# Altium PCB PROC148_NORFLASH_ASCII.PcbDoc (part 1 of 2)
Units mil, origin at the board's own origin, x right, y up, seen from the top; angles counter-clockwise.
Board outline 790 x 790 mil, 6 copper layers (Top Layer, GND1, Signal Layer 1, Signal Layer 2, PWR/GND2, Bottom Layer), stack 65.134 mil thick; 36 components, 63 nets, 233 pads, 102 vias.
Unrouted connection lines stored in the file: 1.
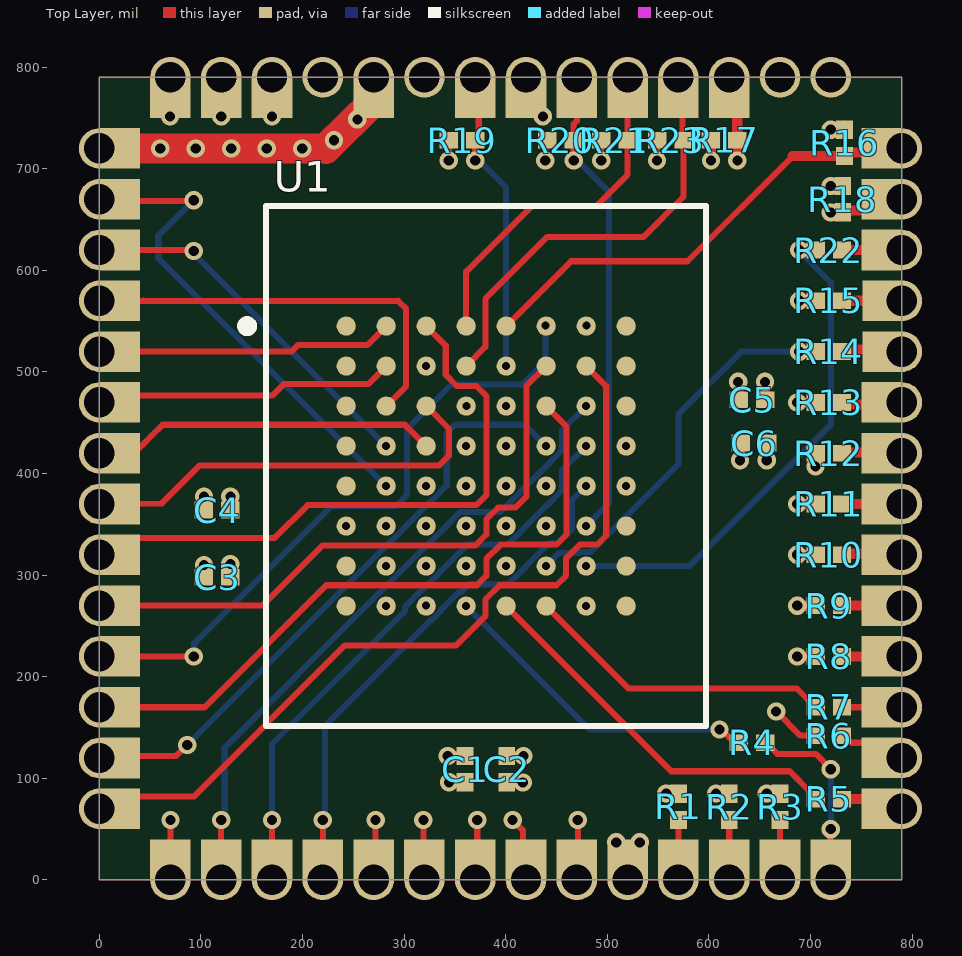
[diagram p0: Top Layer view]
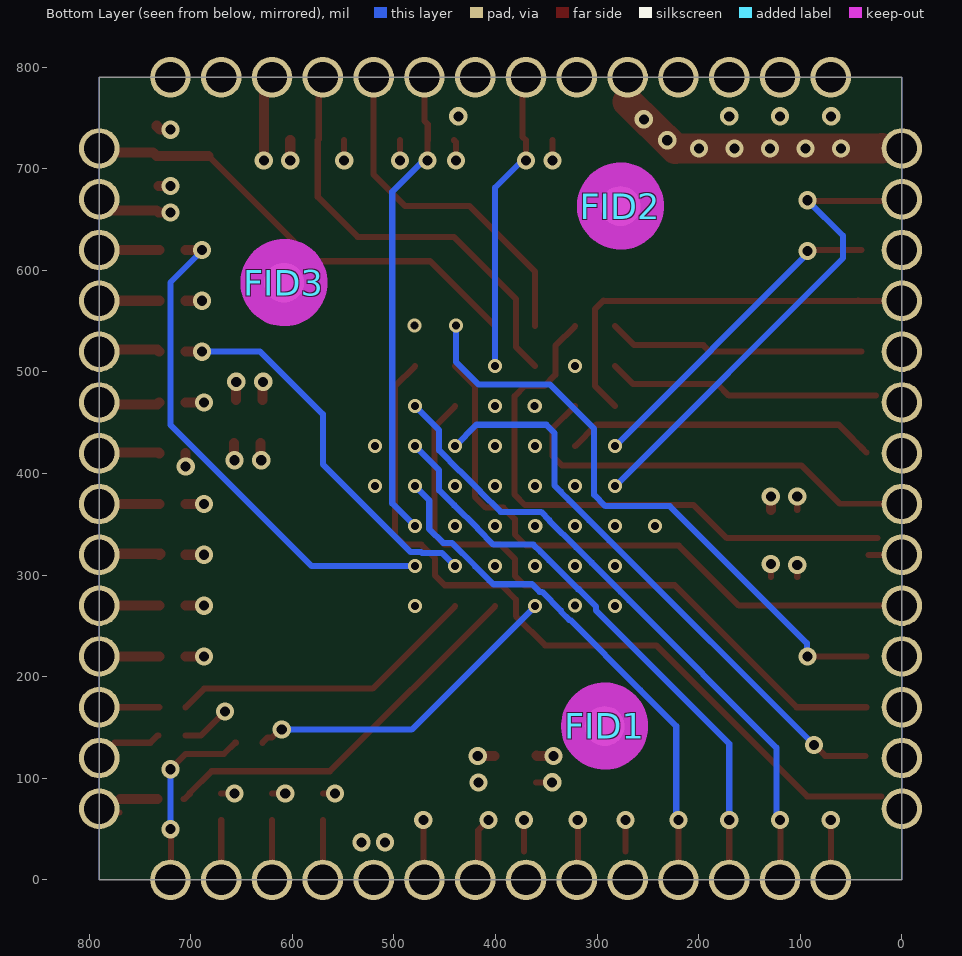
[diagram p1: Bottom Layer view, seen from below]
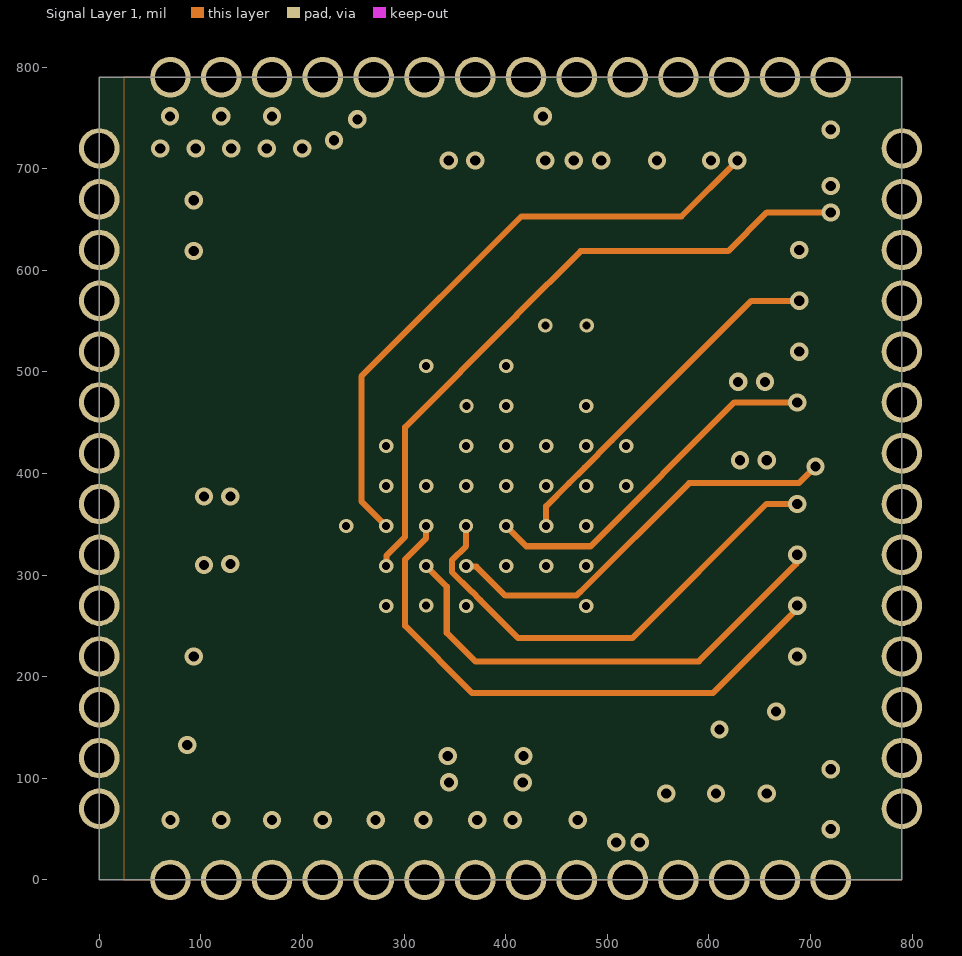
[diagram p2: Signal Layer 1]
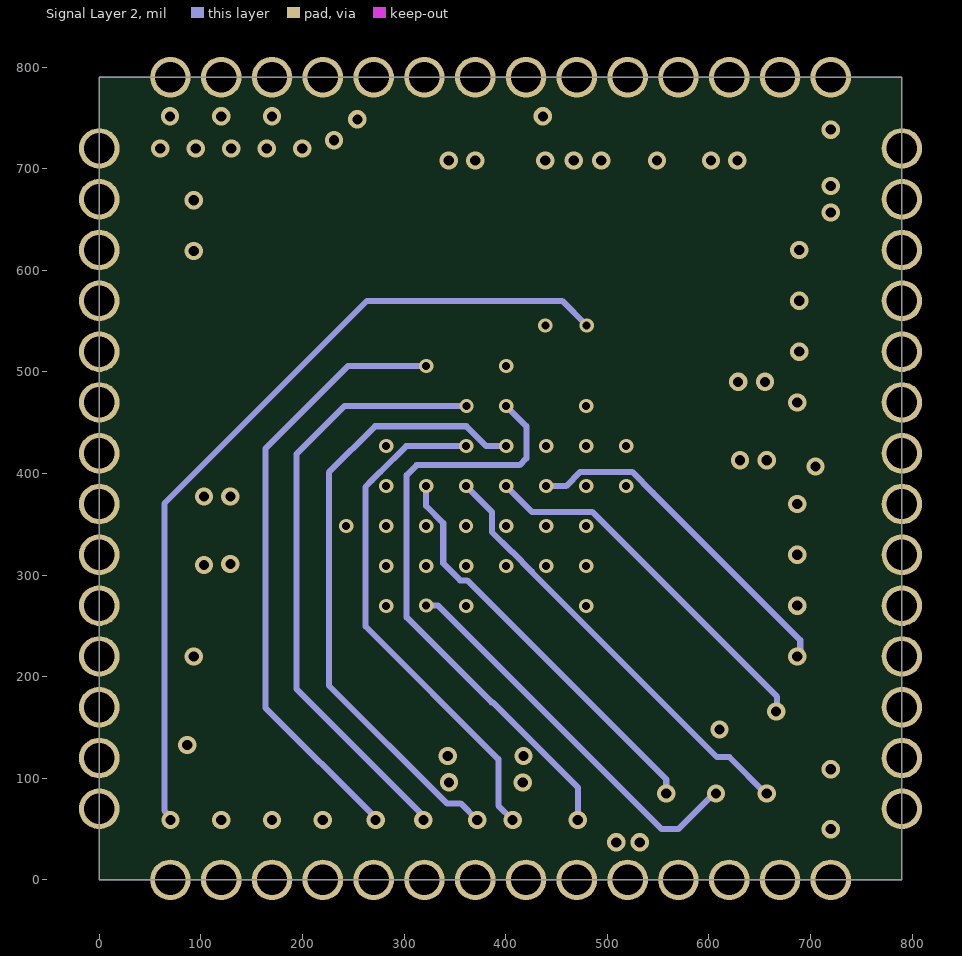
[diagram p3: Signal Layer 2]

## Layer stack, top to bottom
Top Solder: solder mask 0.4, Solder Resist, Dk 3.5
Top Layer: signal copper 0.689
Dielectric 1: prepreg 3.7, FR-4, Dk 4.1
GND1: signal copper 0.689
Dielectric 3: prepreg 2.8, PP-006, Dk 4.1
Signal Layer 1: signal copper 0.689
Dielectric1: core 48, FR-4, Dk 4.8
Signal Layer 2: signal copper 0.689
Dielectric 4: prepreg 2.8, PP-006, Dk 4.1
PWR/GND2: signal copper 0.689
Dielectric 2: prepreg 3.7, FR-4, Dk 4.1
Bottom Layer: signal copper 0.689
Bottom Solder: solder mask 0.4, Solder Resist, Dk 3.5

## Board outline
0,0 790,0 790,790 0,790

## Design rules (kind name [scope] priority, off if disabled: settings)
AcuteAngle [All] p0: scope1count=1 scope1_0_kind=Board scope1_0_value=Board scope2count=1 scope2_0_kind=Board scope2_0_value=Board commentlength=0 minimum=4.50000000000000E+0001
AcuteAngle [All] p1: minimum=4.50000000000000E+0001 checktracksonly=FALSE
AssemblyTestPointUsage [All] p0: scope1count=1 scope1_0_kind=Board scope1_0_value=Board scope2count=1 scope2_0_kind=Board scope2_0_value=Board commentlength=0
AssemblyTestPointUsage [All] p1: valid=2
AssemblyTestpoint [All] p0: scope1count=1 scope1_0_kind=Board scope1_0_value=Board scope2count=1 scope2_0_kind=Board scope2_0_value=Board commentlength=0
BoardOutlineClearance [All] p0 off: scope1count=1 scope1_0_kind=Board scope1_0_value=Board scope2count=1 scope2_0_kind=Board scope2_0_value=Board commentlength=172 gap=40 // Protel DXP Scope 1 Expression Was: OnCopper and Not InComponentClass('Logo') and not InComponentClass('FiducialMark') and not InRegion(1000,500,4000,800) and not InPoly
BoardOutlineClearance BoardOutlineClearance_Poly [All] p0 off: scope1count=1 scope1_0_kind=Board scope1_0_value=Board scope2count=1 scope2_0_kind=Board scope2_0_value=Board commentlength=58 gap=20 // Protel DXP Scope 1 Expression Was: OnCopper and IsPoly
BoardOutlineClearance BoardOutlineClearance_MountingHoles [All] p0 off: scope1count=1 scope1_0_kind=Board scope1_0_value=Board scope2count=1 scope2_0_kind=Board scope2_0_value=Board commentlength=86 gap=39.37 // Protel DXP Scope 1 Expression Was: OnCopper and InComponentClass('Mounting Holes')
BoardOutlineClearance BoardOutlineClearance_MountingHoles [OnCopper and InComponentClass('Mounting Holes')] p1: gap=39.37 ignorepadtopadclearanceinfootprint=FALSE
BoardOutlineClearance BoardOutlineClearance_Poly [OnCopper and IsPoly] p2: gap=20 ignorepadtopadclearanceinfootprint=FALSE
BoardOutlineClearance [OnCopper and Not InComponentClass('Logo') and not InComponentClass('FiducialMark') and not InRegion(1000,500,4000,800) and not InPoly] p3: gap=40 ignorepadtopadclearanceinfootprint=FALSE
Clearance [All] p0: scope1count=1 scope1_0_kind=Board scope1_0_value=Board scope2count=1 scope2_0_kind=Board scope2_0_value=Board commentlength=0 gap=4
Clearance Clearance_FiducialMark [All] p0 off: scope1count=1 scope1_0_kind=Board scope1_0_value=Board scope2count=1 scope2_0_kind=Board scope2_0_value=Board commentlength=81 gap=0 // Protel DXP Scope 2 Expression Was: IsPad and InComponentClass('FiducialMark')
Clearance Clearance_Poly [All] p0 off: scope1count=1 scope1_0_kind=Board scope1_0_value=Board scope2count=1 scope2_0_kind=Board scope2_0_value=Board commentlength=48 gap=4 // Protel DXP Scope 1 Expression Was: InPolygon
Clearance Clearance_Keepouts [All] p0 off: scope1count=1 scope1_0_kind=Board scope1_0_value=Board scope2count=1 scope2_0_kind=Board scope2_0_value=Board commentlength=99 gap=0 // Protel DXP Scope 2 Expression Was: ((IsTrack Or IsArc) And Not InPoly) And IsFree and IsKeepOut
Clearance Clearance_Keepouts [((IsTrack Or IsArc) And Not InPoly) And IsFree and IsKeepOut vs ((IsTrack Or IsArc) And Not InPoly) And IsFree and IsKeepOut] p1: gap=0 ignorepadtopadclearanceinfootprint=FALSE
Clearance Clearance_Poly [InPolygon] p2: gap=4 ignorepadtopadclearanceinfootprint=TRUE except(10: Arc-Arc Arc-Track Arc-SMDPad Arc-THPad Arc-Text Arc-Hole Track-Track Track-SMDPad Track-THPad Track-Text Track-Hole SMDPad-SMDPad SMDPad-THPad SMDPad-Text SMDPad-Hole THPad-THPad THPad-Text THPad-Hole Text-Text Text-Hole)
Clearance Clearance_FiducialMark [IsKeepOut and InComponentClass('FiducialMark') vs IsPad and InComponentClass('FiducialMark')] p3: gap=0 ignorepadtopadclearanceinfootprint=FALSE
Clearance [All] p4: gap=4 ignorepadtopadclearanceinfootprint=TRUE
ComponentClearance [All] p0: scope1count=1 scope1_0_kind=Board scope1_0_value=Board scope2count=1 scope2_0_kind=Board scope2_0_value=Board commentlength=0 gap=20 collisioncheckmode=3
ComponentClearance ComponentClearance_THtoTH [All] p0 off: scope1count=1 scope1_0_kind=Board scope1_0_value=Board scope2count=1 scope2_0_kind=Board scope2_0_value=Board commentlength=54 gap=20 collisioncheckmode=3 // Protel DXP Scope 2 Expression Was: IsThruComponent
ComponentClearance ComponentClearance_THtoSMT [All] p0 off: scope1count=1 scope1_0_kind=Board scope1_0_value=Board scope2count=1 scope2_0_kind=Board scope2_0_value=Board commentlength=53 gap=30 collisioncheckmode=3 // Protel DXP Scope 2 Expression Was: IsSMTComponent
ComponentClearance ComponentClearance_SmallPassives [All] p0 off: scope1count=1 scope1_0_kind=Board scope1_0_value=Board scope2count=1 scope2_0_kind=Board scope2_0_value=Board commentlength=508 gap=14.96 collisioncheckmode=3 // Protel DXP Scope 2 Expression Was: HasFootprint('0201*') or HasFootprint('0402*') or HasFootprint('0508') or HasFootprint('0603*') or HasFootprint('0612') or HasFootprint('0805*') or HasFootprint('0815*') or HasFootprint('0830*') or HasFootprint('1206*') or HasFootprint('1210*') or HasFootprint('1808*') or HasFootprint('1812*') or HasFootprint('1825*') or HasFootprint('2010*') or HasFootprint('2220*') or HasFootprint('2225*') or HasFootprint('2512*') or HasFootprint('2728*') or HasFootprint('3518*')
ComponentClearance ComponentClearance_MountingHoles [All] p0: scope1count=1 scope1_0_kind=ComponentClass scope1_0_value="Mounting Holes" scope2count=1 scope2_0_kind=Board scope2_0_value=Board commentlength=0 gap=100 collisioncheckmode=3
ComponentClearance ComponentClearance_ScrewToNut [All] p0 off: scope1count=1 scope1_0_kind=Board scope1_0_value=Board scope2count=1 scope2_0_kind=Board scope2_0_value=Board commentlength=71 gap=5 collisioncheckmode=3 // Protel DXP Scope 2 Expression Was: (HasFootprint('Keystone_1902C'))
ComponentClearance ComponentClearance_Logo [All] p0: scope1count=1 scope1_0_kind=ComponentClass scope1_0_value=Logo scope2count=1 scope2_0_kind=Board scope2_0_value=Board commentlength=0 gap=30 collisioncheckmode=3
ComponentClearance ComponentClearance_Shunt [All] p0: scope1count=1 scope1_0_kind=ComponentClass scope1_0_value=Header scope2count=1 scope2_0_kind=ComponentClass scope2_0_value=Shunt commentlength=0 gap=0 collisioncheckmode=3
ComponentClearance ComponentClearance_MountingHoles_FiducialMarks [All] p0: scope1count=1 scope1_0_kind=ComponentClass scope1_0_value="Mounting Holes" scope2count=1 scope2_0_kind=ComponentClass scope2_0_value=FiducialMark commentlength=0 gap=50 collisioncheckmode=3
ComponentClearance ComponentClearance_MountingHoles_FiducialMarks [InComponentClass('Mounting Holes') vs InComponentClass('FiducialMark')] p1: gap=50 collisioncheckmode=3 verticalgap=10 showdistances=FALSE
ComponentClearance ComponentClearance_Shunt [InComponentClass('Header') vs InComponentClass('Shunt')] p2: gap=0 collisioncheckmode=3 verticalgap=0 showdistances=FALSE
ComponentClearance ComponentClearance_Logo [InComponentClass('Logo')] p3: gap=30 collisioncheckmode=3 verticalgap=10 showdistances=FALSE
ComponentClearance ComponentClearance_ScrewToNut [(HasFootprint('NY PMS 440 0025 PH')) vs (HasFootprint('Keystone_1902C'))] p4: gap=5 collisioncheckmode=3 verticalgap=10 showdistances=FALSE
ComponentClearance ComponentClearance_MountingHoles [InComponentClass('Mounting Holes')] p5: gap=100 collisioncheckmode=3 verticalgap=100000 showdistances=FALSE
ComponentClearance ComponentClearance_SmallPassives [HasFootprint('0201*') or HasFootprint('0402*') or HasFootprint('0508') or HasFootprint('0603*') or HasFootprint('0612') or HasFootprint('0805*') or HasFootprint('0815*') or HasFootprint('0830*') or HasFootprint('1206*') or HasFootprint('1210*') or HasFootprint('1808*') or HasFootprint('1812*') or HasFootprint('1825*') or HasFootprint('2010*') or HasFootprint('2220*') or HasFootprint('2225*') or HasFootprint('2512*') or HasFootprint('2728*') or HasFootprint('3518*') vs HasFootprint('0201*') or HasFootprint('0402*') or HasFootprint('0508') or HasFootprint('0603*') or HasFootprint('0612') or HasFootprint('0805*') or HasFootprint('0815*') or HasFootprint('0830*') or HasFootprint('1206*') or HasFootprint('1210*') or HasFootprint('1808*') or HasFootprint('1812*') or HasFootprint('1825*') or HasFootprint('2010*') or HasFootprint('2220*') or HasFootprint('2225*') or HasFootprint('2512*') or HasFootprint('2728*') or HasFootprint('3518*')] p6: gap=14.96 collisioncheckmode=3 verticalgap=10 showdistances=FALSE
ComponentClearance ComponentClearance_THtoSMT [IsThruComponent vs IsSMTComponent] p7: gap=30 collisioncheckmode=3 verticalgap=30 showdistances=FALSE
ComponentClearance ComponentClearance_THtoTH [IsThruComponent vs IsThruComponent] p8: gap=20 collisioncheckmode=3 verticalgap=30 showdistances=FALSE
ComponentClearance [All] p9: gap=20 collisioncheckmode=3 verticalgap=10 showdistances=FALSE
DiffPairsRouting [All] p0: scope1count=1 scope1_0_kind=Board scope1_0_value=Board scope2count=1 scope2_0_kind=Board scope2_0_value=Board commentlength=0
DiffPairsRouting [All] p1: maxlimit=100 minlimit=10 mostfreqgap=10 toplayer_minwidth=15 toplayer_maxwidth=15 toplayer_prefwidth=15 midlayer1_minwidth=15 midlayer1_maxwidth=15 midlayer1_prefwidth=15 midlayer2_minwidth=15 midlayer2_maxwidth=15 midlayer2_prefwidth=15 midlayer3_minwidth=15 midlayer3_maxwidth=15 midlayer3_prefwidth=15 midlayer4_minwidth=15 midlayer4_maxwidth=15 midlayer4_prefwidth=15 bottomlayer_minwidth=15 bottomlayer_maxwidth=15 bottomlayer_prefwidth=15 maxuncoupledlength=1000
FabricationTestPointUsage TestPointUsage [All] p0: scope1count=1 scope1_0_kind=Board scope1_0_value=Board scope2count=1 scope2_0_kind=Board scope2_0_value=Board commentlength=0 valid=2 allowmultiple=FALSE
FabricationTestPointUsage TestPointUsage [All] p1: valid=2 allowmultiple=FALSE
FabricationTestpoint Testpoint [All] p0: scope1count=1 scope1_0_kind=Board scope1_0_value=Board scope2count=1 scope2_0_kind=Board scope2_0_value=Board commentlength=0 side=3 testpointundercomponent=TRUE minsize=40 maxsize=100 preferedsize=60 minholesize=0 maxholesize=40 preferedholesize=32 testpointgrid=1
FabricationTestpoint Testpoint [All] p1: side=3 testpointundercomponent=TRUE minsize=40 maxsize=100 preferedsize=60 minholesize=0 maxholesize=40 preferedholesize=32 testpointgrid=1 allowsidetop=TRUE allowsidebottom=TRUE usegrid=TRUE gridtolerance=0.01
FanoutControl Fanout_Small [All] p0 off: scope1count=1 scope1_0_kind=Board scope1_0_value=Board scope2count=1 scope2_0_kind=Board scope2_0_value=Board commentlength=84 // Protel DXP Scope 1 Expression Was: (CompPinCount < 5)   Fanout_Small (Default Rule)
FanoutControl Fanout_Default [All] p0: scope1count=1 scope1_0_kind=Board scope1_0_value=Board scope2count=1 scope2_0_kind=Board scope2_0_value=Board commentlength=30 // Fanout_Default (Default Rule)
FanoutControl Fanout_SOIC [All] p0 off: scope1count=1 scope1_0_kind=Board scope1_0_value=Board scope2count=1 scope2_0_kind=Board scope2_0_value=Board commentlength=71 // Protel DXP Scope 1 Expression Was: IsSOIC   Fanout_SOIC (Default Rule)
FanoutControl Fanout_BGA [All] p0 off: scope1count=1 scope1_0_kind=Board scope1_0_value=Board scope2count=1 scope2_0_kind=Board scope2_0_value=Board commentlength=69 // Protel DXP Scope 1 Expression Was: IsBGA   Fanout_BGA (Default Rule)
FanoutControl Fanout_LCC [All] p0 off: scope1count=1 scope1_0_kind=Board scope1_0_value=Board scope2count=1 scope2_0_kind=Board scope2_0_value=Board commentlength=69 // Protel DXP Scope 1 Expression Was: IsLCC   Fanout_LCC (Default Rule)
FanoutControl Fanout_LCC [IsLCC] p1: bgadir=Out bgaviamode=Centered fanoutstyle=Auto fanoutdirection=Alternating viagrid=1 // Fanout_LCC (Default Rule)
FanoutControl Fanout_BGA [IsBGA] p2: bgadir=Out bgaviamode=Centered fanoutstyle=Auto fanoutdirection=Alternating viagrid=1 // Fanout_BGA (Default Rule)
FanoutControl Fanout_Default [All] p4: bgadir=Out bgaviamode=Centered fanoutstyle=Auto fanoutdirection=Alternating viagrid=1 // Fanout_Default (Default Rule)
FanoutControl Fanout_Small [(CompPinCount < 5)] p5: bgadir=Out bgaviamode=Centered fanoutstyle=Auto fanoutdirection=OutThenIn viagrid=1 // Fanout_Small (Default Rule)
Height [All] p0: scope1count=1 scope1_0_kind=Board scope1_0_value=Board scope2count=1 scope2_0_kind=Board scope2_0_value=Board commentlength=0
HoleSize [All] p0: scope1count=1 scope1_0_kind=Board scope1_0_value=Board scope2count=1 scope2_0_kind=Board scope2_0_value=Board commentlength=0 absolutevalues=TRUE maxlimit=251 minlimit=7 maxpercent=80.000 minpercent=20.000
HoleSize [All] p1: absolutevalues=TRUE maxlimit=251 minlimit=7 maxpercent=80.000 minpercent=20.000
HoleToHoleClearance [All] p0: scope1count=1 scope1_0_kind=Board scope1_0_value=Board scope2count=1 scope2_0_kind=Board scope2_0_value=Board commentlength=0
HoleToHoleClearance [All] p1: gap=6 allowstackedmicrovias=TRUE
LayerPairs [All] p0: scope1count=1 scope1_0_kind=Board scope1_0_value=Board scope2count=1 scope2_0_kind=Board scope2_0_value=Board commentlength=0 enforce=TRUE
MinimumAnnularRing [All] p0: scope1count=1 scope1_0_kind=Board scope1_0_value=Board scope2count=1 scope2_0_kind=Board scope2_0_value=Board commentlength=0 minimumring=3
MinimumAnnularRing MinimumAnnularRing_ThermalPadVias [All] p0 off: scope1count=1 scope1_0_kind=Board scope1_0_value=Board scope2count=1 scope2_0_kind=Board scope2_0_value=Board commentlength=63 minimumring=5.91 // Protel DXP Scope 1 Expression Was: IsVia and InAnyComponent
MinimumAnnularRing MinimumAnnularRing_ThermalPadVias [IsVia and InAnyComponent] p1: minimumring=5.91
MinimumAnnularRing [All] p2: minimumring=3
MinimumSolderMaskSliver [All] p0: scope1count=1 scope1_0_kind=Board scope1_0_value=Board scope2count=1 scope2_0_kind=Board scope2_0_value=Board commentlength=0
MinimumSolderMaskSliver MinimumSolderMaskSliver_Logo [All] p0: scope1count=1 scope1_0_kind=ComponentClass scope1_0_value=Logo scope2count=1 scope2_0_kind=ComponentClass scope2_0_value=Logo commentlength=0
MinimumSolderMaskSliver MinimumSolderMaskSliver_Logo [InComponentClass('Logo') vs InComponentClass('Logo')] p1: minsoldermaskwidth=0.7
MinimumSolderMaskSliver [All] p2: minsoldermaskwidth=3
NetAntennae [All] p0: scope1count=1 scope1_0_kind=Board scope1_0_value=Board scope2count=1 scope2_0_kind=Board scope2_0_value=Board commentlength=0
PasteMaskExpansion [All] p0: scope1count=1 scope1_0_kind=Board scope1_0_value=Board scope2count=1 scope2_0_kind=Board scope2_0_value=Board commentlength=0 expansion=0
PlaneClearance [All] p0: scope1count=1 scope1_0_kind=Board scope1_0_value=Board scope2count=1 scope2_0_kind=Board scope2_0_value=Board commentlength=0 clearance=20
PlaneConnect [All] p0: scope1count=1 scope1_0_kind=Board scope1_0_value=Board scope2count=1 scope2_0_kind=Board scope2_0_value=Board commentlength=0 planeconnectstyle=Relief reliefexpansion=10 reliefentries=4 reliefconductorwidth=10 reliefairgap=10
PlaneConnect [All] p1: planeconnectstyle=Relief reliefexpansion=10 reliefentries=4 reliefconductorwidth=10 reliefairgap=10
PolygonConnect [All] p0: scope1count=1 scope1_0_kind=Board scope1_0_value=Board scope2count=1 scope2_0_kind=Board scope2_0_value=Board commentlength=0 connectstyle=Direct reliefconductorwidth=10 reliefentries=4 polygonreliefangle="90 Angle"
PolygonConnect [All] p1: connectstyle=Direct reliefconductorwidth=10 reliefentries=4 polygonreliefangle="90 Angle" airgapwidth=10
RoutingCorners [All] p0: scope1count=1 scope1_0_kind=Board scope1_0_value=Board scope2count=1 scope2_0_kind=Board scope2_0_value=Board commentlength=0 cornerstyle=45-Degree minsetback=100 maxsetback=100
RoutingLayers [All] p0: scope1count=1 scope1_0_kind=Board scope1_0_value=Board scope2count=1 scope2_0_kind=Board scope2_0_value=Board commentlength=0 top layer=Automatic mid layer 1=Automatic mid layer 2=Automatic mid layer 3=Automatic mid layer 4=Automatic bottom layer=Automatic
RoutingPriority [All] p0: scope1count=1 scope1_0_kind=Board scope1_0_value=Board scope2count=1 scope2_0_kind=Board scope2_0_value=Board commentlength=0
RoutingTopology [All] p0: scope1count=1 scope1_0_kind=Board scope1_0_value=Board scope2count=1 scope2_0_kind=Board scope2_0_value=Board commentlength=0 topology=Shortest
RoutingVias [All] p0: scope1count=1 scope1_0_kind=Board scope1_0_value=Board scope2count=1 scope2_0_kind=Board scope2_0_value=Board commentlength=0 holewidth=16 width=34 viastyle="Through Hole" minholewidth=7.87 minwidth=14 maxholewidth=40 maxwidth=65
RoutingVias ThermalPadVias [All] p0 off: scope1count=1 scope1_0_kind=Board scope1_0_value=Board scope2count=1 scope2_0_kind=Board scope2_0_value=Board commentlength=63 holewidth=7.87 width=19.68 viastyle="Through Hole" minholewidth=7.87 minwidth=19.68 maxholewidth=12.99 maxwidth=23.62 // Protel DXP Scope 1 Expression Was: IsVia and InAnyComponent
RoutingVias ThermalPadVias [IsVia and InAnyComponent] p1: holewidth=7.87 width=19.68 viastyle="Through Hole" minholewidth=7.87 minwidth=19.68 maxholewidth=12.99 maxwidth=23.62
RoutingVias [All] p2: holewidth=16 width=34 viastyle="Through Hole" minholewidth=7.87 minwidth=14 maxholewidth=40 maxwidth=65
ShortCircuit [All] p0: scope1count=1 scope1_0_kind=Board scope1_0_value=Board scope2count=1 scope2_0_kind=Board scope2_0_value=Board commentlength=0 allowed=FALSE
SilkToBoardRegionClearance [All] p0 off: scope1count=1 scope1_0_kind=Board scope1_0_value=Board scope2count=1 scope2_0_kind=Board scope2_0_value=Board commentlength=130 // Protel DXP Scope 1 Expression Was: Not ((IsComment or IsDesignator) And (Hide <> 'False')) and not InRegion(1000,500,4000,800)
SilkToBoardRegionClearance [Not ((IsComment or IsDesignator) And (Hide <> 'False')) and not InRegion(1000,500,4000,800)] p1:
SilkToSilkClearance [All] p0: scope1count=1 scope1_0_kind=Board scope1_0_value=Board scope2count=1 scope2_0_kind=Board scope2_0_value=Board commentlength=0
SilkToSilkClearance SilkToSilkClearance_Pb-FreeLogo [All] p0 off: scope1count=1 scope1_0_kind=Board scope1_0_value=Board scope2count=1 scope2_0_kind=Board scope2_0_value=Board commentlength=120 // Protel DXP Scope 2 Expression Was: (HasFootprint('Pb-Free_Overlay_Medium') OR HasFootprint('Pb-Free_Overlay_Small'))
SilkToSilkClearance SilkToSilkClearance_Pb-FreeLogo [(HasFootprint('Pb-Free_Overlay_Medium') OR HasFootprint('Pb-Free_Overlay_Small')) vs (HasFootprint('Pb-Free_Overlay_Medium') OR HasFootprint('Pb-Free_Overlay_Small'))] p1: silktosilkclearance=0
SilkToSilkClearance [All] p2: silktosilkclearance=3.94
SilkToSolderMaskClearance "Silk to Solder Mask Opening" [All] p0: scope1count=1 scope1_0_kind=Board scope1_0_value=Board scope2count=1 scope2_0_kind=Board scope2_0_value=Board commentlength=0
SilkToSolderMaskClearance SilkToComponentPadClearance [All] p0 off: scope1count=1 scope1_0_kind=Board scope1_0_value=Board scope2count=1 scope2_0_kind=Board scope2_0_value=Board commentlength=87 // Protel DXP Scope 1 Expression Was: (IsPad or IsFill or IsRegion) and InAnycomponent
SilkToSolderMaskClearance SilkToComponentPadClearance [(IsPad or IsFill or IsRegion) and InAnycomponent] p1: minsilkscreentomaskgap=5 clearancetoexposedcopper=TRUE
SilkToSolderMaskClearance "Silk to Solder Mask Opening" [All] p2: minsilkscreentomaskgap=3 clearancetoexposedcopper=FALSE
SolderMaskExpansion [All] p0: scope1count=1 scope1_0_kind=Board scope1_0_value=Board scope2count=1 scope2_0_kind=Board scope2_0_value=Board commentlength=0 expansion=1.97
SolderMaskExpansion [All] p1: expansion=1.97 istentingtop=FALSE
UnRoutedNet [All] p0: scope1count=1 scope1_0_kind=Board scope1_0_value=Board scope2count=1 scope2_0_kind=Board scope2_0_value=Board commentlength=0
UnRoutedNet [All] p1: checkbadconnections=TRUE
UnpouredPolygon [All] p0: scope1count=1 scope1_0_kind=Board scope1_0_value=Board scope2count=1 scope2_0_kind=Board scope2_0_value=Board commentlength=0
Width [All] p0: scope1count=1 scope1_0_kind=Board scope1_0_value=Board scope2count=1 scope2_0_kind=Board scope2_0_value=Board commentlength=0 maxlimit=100 minlimit=6 preferedwidth=10
Width [All] p1: maxlimit=100 minlimit=6 preferedwidth=10 checkconnectedcopper=TRUE
13 further rules are at their usual default settings.

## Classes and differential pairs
component class PROC148_NORFLASH: C1 C2 C3 C4 C5 C6 R1 R2 R3 R4 R5 R6 R7 R8 R9 R10 R11 R12 R13 R14 R15 R16 R17 R19 R20 R21 R22 R23 U1
component class PROC148_NORFLASH_Hardware: FID1 FID2 FID3 ZZ2 ZZ3 ZZ4
component class FiducialMark: FID1 FID2 FID3
component class AssemblyNote: ZZ2 ZZ3 ZZ4

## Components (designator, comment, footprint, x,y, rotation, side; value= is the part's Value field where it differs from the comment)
C1 "GRM033R61C104KE84D" 0201_033 360,109 r270 top
C2 "GRM033R61C103KA12D" 0201_033 401,109 r270 top
C3 "GRM033R61C103KA12D" 0201_033 116,298 r180 top
C4 "GRM033R61C104KE84D" 0201_033 116,364 r180 top
C5 "GRM033R61C103KA12D" 0201_033 642.47,472.53 r0 top
C6 "GRM033R61C104KE84D" 0201_033 644.48,430 r0 top
FID1 "Fiducial" Fiducial10-20 292.6,151.41 r180 bottom
FID2 "Fiducial" Fiducial10-20 277.05,663.22 r180 bottom
FID3 "Fiducial" Fiducial10-20 608.24,587.88 r180 bottom
R1 "ERJ-1GNJ220C" 0201 570,72 r270 top
R2 "ERJ-1GNJ220C" 0201 620,72 r270 top
R3 "ERJ-1GNJ220C" 0201 670,72 r270 top
R4 "ERJ-1GNJ220C" 0201 642.47,135.01 r0 top
R5 "ERJ-1GNJ220C" 0201 718,79.5 r0 top
R6 "ERJ-1GNJ220C" 0201 718,142 r0 top
R7 "ERJ-1GNJ220C" 0201 718,170 r0 top
R8 "ERJ-1GNJ220C" 0201 718,220 r0 top
R9 "ERJ-1GNJ220C" 0201 718,270 r0 top
R10 "ERJ-1GNJ220C" 0201 718,320 r0 top
R11 "ERJ-1GNJ220C" 0201 718,370 r0 top
R12 "ERJ-1GNJ220C" 0201 718,420 r0 top
R13 "ERJ-1GNJ220C" 0201 718,470 r0 top
R14 "ERJ-1GNJ220C" 0201 718,520 r0 top
R15 "ERJ-1GNJ220C" 0201 718,570 r0 top
R16 "RC0201JS-7D10KL" 0201 733.51,725.49 r90 top
R17 "RC0201JS-7D10KL" 0201 615,728 r180 top
R18 "RC0201JS-7D10KL" 0201 731.71,670 r90 top
R19 "RC0201JS-7D10KL" 0201 357,728 r180 top
R20 "RC0201JS-7D10KL" 0201 453.74,728 r180 top
R21 "RC0201JS-7D10KL" 0201 507,728 r180 top
R22 "ERJ-1GNJ220C" 0201 718,620 r0 top
R23 "RC0201JS-7D10KL" 0201 562,728 r180 top
U1 "MT28EW256ABA1LPC-0SIT" FP-MT28EW256ABA1LPC-0SIT_LBGA64-IPC_C 380.8,407.32 r0 top
ZZ2 "These assemblies are ESD sensitive, ESD precautions shall be observed." AssemblyNote -81,2104 r0 top
ZZ3 "These assemblies must be clean and free from flux and all contaminants. Use of no clean flux is not acceptable." AssemblyNote -81,2004 r0 top
ZZ4 "These assemblies must comply with workmanship standards IPC-A-610 Class 2, unless otherwise specified." AssemblyNote -81,1904 r0 top

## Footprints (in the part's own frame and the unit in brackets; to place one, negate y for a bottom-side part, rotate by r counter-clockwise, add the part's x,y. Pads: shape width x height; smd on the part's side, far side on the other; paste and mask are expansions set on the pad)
0201 [mm] "Data from Kemet datasheet CC101_COM dated 7/28/11"
  rect 0.46x0.42 smd mask+0: 1(-0.33,0) 2(0.33,0)
0201_033 [mm] "SMD, 2-Leads, Height 0.33mm"
  rect 0.46x0.42 smd mask+0: 1(-0.33,0) 2(0.33,0)
AssemblyNote [mil] "Assembly Note"
Fiducial10-20 [mm]
  round 1 smd mask+0: 1(0,0)
  Top Layer keep-out circle w1.178: c0,0 r0.5
FP-MT28EW256ABA1LPC-0SIT_LBGA64-IPC_C [mm]
  round 0.48 smd paste+0 mask+0: A1(-3.5,3.5) A2(-2.5,3.5) A3(-1.5,3.5) A4(-0.5,3.5) A5(0.5,3.5) A6(1.5,3.5) A7(2.5,3.5) A8(3.5,3.5) B1(-3.5,2.5) B2(-2.5,2.5) B3(-1.5,2.5) B4(-0.5,2.5) B5(0.5,2.5) B6(1.5,2.5) B7(2.5,2.5) B8(3.5,2.5) C1(-3.5,1.5) C2(-2.5,1.5) C3(-1.5,1.5) C4(-0.5,1.5) C5(0.5,1.5) C6(1.5,1.5) C7(2.5,1.5) C8(3.5,1.5) D1(-3.5,0.5) D2(-2.5,0.5) D3(-1.5,0.5) D4(-0.5,0.5) D5(0.5,0.5) D6(1.5,0.5) D7(2.5,0.5) D8(3.5,0.5) E1(-3.5,-0.5) E2(-2.5,-0.5) E3(-1.5,-0.5) E4(-0.5,-0.5) E5(0.5,-0.5) E6(1.5,-0.5) E7(2.5,-0.5) E8(3.5,-0.5) F1(-3.5,-1.5) F2(-2.5,-1.5) F3(-1.5,-1.5) F4(-0.5,-1.5) F5(0.5,-1.5) F6(1.5,-1.5) F7(2.5,-1.5) F8(3.5,-1.5) G1(-3.5,-2.5) G2(-2.5,-2.5) G3(-1.5,-2.5) G4(-0.5,-2.5) G5(0.5,-2.5) G6(1.5,-2.5) G7(2.5,-2.5) G8(3.5,-2.5) H1(-3.5,-3.5) H2(-2.5,-3.5) H3(-1.5,-3.5) H4(-0.5,-3.5) H5(0.5,-3.5) H6(1.5,-3.5) H7(2.5,-3.5) H8(3.5,-3.5)
  silkscreen extent -6.1,-6.5 5.5,6.5

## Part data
C1 C4 C6: library part CMP-0009717-2, "CAP, CERM, 0.1 uF, 16 V, +/- 10%, X5R, 0201"
C2 C3 C5: library part CMP-0009716-1, "CAP, CERM, 0.01 uF, 16 V, +/- 10%, X5R, 0201"
FID1 FID2 FID3: library part CMP-0077181-1, "Fiducial mark.  There is nothing to buy or mount."
R1 R2 R3 R4 R5 R6 R7 R8 R9 R10 R11 R12 R13 R14 R15 R22: library part CMP-0027015-2, "RES, 22, 5%, 0.05 W, AEC-Q200 Grade 1, 0201"
R16 R17 R18 R19 R20 R21 R23: library part CMP-0027260-1, "RES, 10 k, 5%, 0.05 W, 0201"
U1: library part CMP-0095868-1, "FLASH - NOR Memory IC 256Mb (32M x 8, 16M x 16) Parallel 75 ns 64-LBGA (11x13)"
ZZ2: library part CMP-0077236-1
ZZ3: library part CMP-0077237-1
ZZ4: library part CMP-0077238-1

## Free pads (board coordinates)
  round 40 hole 30: 3(0,70) 3(0,120) 3(0,170) 3(0,220) 3(0,270) 3(0,320) 3(0,370) 3(0,420) 3(0,470) 3(0,520) 3(0,570) 3(0,620) 3(0,670) 3(0,720) 3(70,0) 3(70,790) 3(120,0) 3(120,790) 3(170,0) 3(170,790) 3(220,0) 3(220,790) 3(270,0) 3(270,790) 3(320,0) 3(320,790) 3(370,0) 3(370,790) 3(420,0) 3(420,790) 3(470,0) 3(470,790) 3(520,0) 3(520,790) 3(570,0) 3(570,790) 3(620,0) 3(620,790) 3(670,0) 3(670,790) 3(720,0) 3(720,790) 3(790,70) 3(790,120) 3(790,170) 3(790,220) 3(790,270) 3(790,320) 3(790,370) 3(790,420) 3(790,470) 3(790,520) 3(790,570) 3(790,620) 3(790,670) 3(790,720)
  rect 40x40 smd mask+0: 4(19.86,720) 4(20,70) 4(20,120) 4(20,170) 4(20,220) 4(20,270) 4(20,320) 4(20,370) 4(20,420) 4(20,470) 4(20,520) 4(20,570) 4(20,620) 4(20,670) 4(70,20) 4(70,770) 4(120,20) 4(120,770) 4(170,20) 4(170,770) 4(220,20) 4(270,20) 4(270,770) 4(320,20) 4(370,20) 4(370,770) 4(420,20) 4(420,770) 4(470,20) 4(470,770) 4(519.99,770) 4(520,20) 4(570,20) 4(570,770) 4(620,20) 4(620,770) 4(670,20) 4(720,20) 4(770,70) 4(770,120.14) 4(770,170) 4(770,220) 4(770,270) 4(770,320) 4(770,370) 4(770,420) 4(770,470) 4(770,620) 4(770,670) 4(770,720) 4(771,520) 4(771,570)

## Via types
v1: diameter 18, hole 10, Top Layer to Bottom Layer, tented both sides, 65 vias
v2: diameter 14, hole 7.87, Top Layer to Bottom Layer, tented both sides, 37 vias

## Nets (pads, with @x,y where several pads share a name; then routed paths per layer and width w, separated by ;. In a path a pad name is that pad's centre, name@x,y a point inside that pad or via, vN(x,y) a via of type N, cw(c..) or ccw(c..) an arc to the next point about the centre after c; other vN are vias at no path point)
GND: C1.2 C2.2 C3.2 C4.2 C5.2 C6.2 pad.3@70,790 pad.3@120,790 pad.3@170,790 pad.3@420,790 pad.3@520,0 pad.4@70,770 pad.4@120,770 pad.4@170,770 pad.4@420,770 pad.4@520,20 U1.E8 U1.H2 U1.H7 | length 71.5
  Top Layer w6: C3.2@103.01,298 v1(103,310) ; C4.2@103.01,364 v1(103.01,377.29) ; v1(344.25,96.01) C1.2@360,96.01
  Top Layer w10: C5.2@655.47,472.53 v1@655.47,488 ; v1@657.47,415 C6.2@657.47,430
  other v1: 508.84,37 532,37 416.75,95.93 657,413 655.23,490.24 69.66,751.54 120,751.54 170,751.54 436.59,751.54
  other v2: 282.37,269.52 479.22,269.52 518.59,387.63
GPMC0_A0_MUX: pad.3@0,670 pad.4@20,670 U1.E2 | length 462.3
  Top Layer w6: pad.4@19.86,668.09 92.09,668.09 v1(93,669)
  Bottom Layer w6: v1(93,669) 58,634 58,612 v2(282.37,387.63)
GPMC0_A1_MUX: pad.3@0,620 pad.4@20,620 U1.D2 | length 323
  Top Layer w6: 40,619.91 92.09,619.91 v1(93,619)
  Bottom Layer w6: v1@91.68,617.69 v2(282.37,427)
GPMC0_A2_MUX: pad.3@0,570 pad.4@20,570 U1.C2 | length 389.1
  Top Layer w6: pad.4@20,570 293.91,570.09 302,562 302,486 U1.C2@282.37,466.37
GPMC0_A3_MUX: pad.3@0,520 pad.4@20,520 U1.A2 | length 252.8
  Top Layer w6: 40,520.09 189.15,520 195.47,526.32 263.58,526.32 U1.A2@282.37,545.11
GPMC0_A4_MUX: pad.3@0,470 pad.4@20,470 U1.B2 | length 268.9
  Top Layer w6: pad.4@25.49,476.77 170.28,476.77 181.51,488 264.63,488 U1.B2@282.37,505.74
GPMC0_A5_MUX: pad.3@0,420 pad.4@20,420 U1.D3 | length 306.9
  Top Layer w6: pad.4@34.86,420.62 39.55,425.31 44.24,430 51.4,437.16 62.24,448 300.74,448 U1.D3@321.74,427
GPMC0_A6_MUX: pad.3@0,370 pad.4@20,370 U1.C3 | length 402.1
  Top Layer w6: pad.4@20,370 61.61,370.6 99.05,408 334.65,408 344.01,417.36 344.01,444.33 321.74,466.6 U1.C3@321.74,466.37
GPMC0_A7_MUX: pad.3@0,320 pad.4@20,320 U1.A3 | length 609.6
  Top Layer w6: pad.3@0,320 pad.4@20,320 pad.4@32.82,320 ; pad.4@24,336.4 172.37,336.4 204.97,369 371,369 381.19,379.19 381.19,476.18 371.2,486.17 351.83,486.17 341,497 341,525.85 U1.A3@321.74,545.11
GPMC0_A8_MUX: pad.3@0,270 pad.4@20,270 U1.B6 | length 590.1
  Top Layer w6: pad.4@20,270 160.5,270 219.5,329 370,329 381,340 381,355 392.41,366.41 409.41,366.41 420.34,377.34 420.34,486.23 U1.B6@439.85,505.74
GPMC0_A9_MUX: pad.3@0,220 pad.4@20,220 U1.A6 | length 605.3
  Top Layer w6: pad.4@35,220 v1(93,220)
  Bottom Layer w6: v1(93,220) 93.48,220.48 93.48,232.97 228.51,368 291.9,368 303,379.1 303,444.12 346.64,487.76 416.87,487.76 439,509.89 v2(439,545.69)
GPMC0_A10_MUX: pad.3@0,170 pad.4@20,170 U1.C6 | length 639.8
  Top Layer w6: pad.4@35,170 103.6,170 223.6,290 371.59,290 381,299.41 381,316 395,330 450,330 460,340 460,446.22 U1.C6@439.85,466.37
GPMC0_A11_MUX: pad.3@0,120 pad.4@20,120 U1.D6 | length 578.2
  Top Layer w6: pad.4@36,122 75.68,122 v1(86.5,132.82)
  Bottom Layer w6: v1(86.5,132.82) 287.94,334.26 288.17,334.26 307.74,353.83 307.74,354.06 327.31,373.63 327.54,373.63 335.74,381.83 335.74,382.06 342,388.32 342,440.06 349.94,448 418.85,448 v2(439.85,427)
GPMC0_A12_MUX: pad.3@0,70 pad.4@20,70 U1.B7 | length 779.4
  Top Layer w6: pad.4@20.39,82.27 93.27,82.27 241.8,230.8 351.19,230.8 380,259.61 380,276 394,290 450,290 459.54,299.54 459.54,316.54 473,330 490,330 499,339 499,485.96 U1.B7@479.22,505.74
GPMC0_A13_MUX: pad.3@70,0 pad.4@70,20 U1.A7 | length 859.7
  Top Layer w6: pad.4@70,20 v1@70,53
  Signal Layer 2 w6: v1@70,53 v1@73,56 ; v1(70,59) 70,62.25 64,68.25 64,370.49 263.51,570 455.46,570 v2(479.77,545.69)
GPMC0_A14_MUX: pad.3@120,0 pad.4@120,20 U1.C7 | length 619
  Top Layer w6: pad.4@119.69,20 119.69,58.69 v1(120,59)
  Bottom Layer w6: v1(120,59) 120,61.16 123.51,64.68 123.51,130.24 268.37,275.09 268.37,275.32 276.57,283.52 276.8,283.52 305.3,312.02 305.3,312.24 320.4,327.35 320.63,327.35 347,353.72 347,354.06 355.2,362.26 394.91,362.26 414.88,382.23 414.88,382.46 434.85,402.43 435.08,402.43 455.44,422.79 455.44,442.59 v2(479.22,466.37)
